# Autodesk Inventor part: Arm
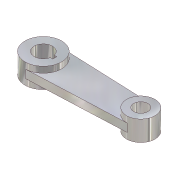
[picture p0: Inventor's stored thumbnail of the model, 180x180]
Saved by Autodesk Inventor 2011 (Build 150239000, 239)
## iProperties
Shininess: 77.0
Length Units: 11269
Angle Units: 11279
Time Units: 11290
Mass Units: 11283
Length Display Precision: 3
Angle Display Precision: 2
Created: 2002-01
Part Number: Arm
Document SubType Name: Modeling
Designer: ***
Density: 1 g/cm^3
Density: 0.0
Volumn: 0.0
Area: 0.0
PropertySet Name: Model Information
Control State: 0
Master: False
Checked Out: False
Author: ***
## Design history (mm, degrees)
sketch "Sketch1"
  geometry: L1 (-12.46, 6.114)-(-4.76, 6.114); L2 (-4.76, 6.114)-(-4.76, -6.486); L3 (-4.76, -6.486)-(-12.46, -6.486); L4 (-12.46, -6.486)-(-12.46, -6.885); C1 r 56.25 at (-39.849, -0.386); C2 r 43.75 at (260.151, -0.142); C3 r 21.9 at (260.151, -0.142); A1 r 28.15 centre (-39.849, -0.386) between (-12.46, 6.114) and (-12.46, -6.885)
  constraints: 8 end point, 4 centre point, 3 parallel, 2 coincident, 2 point on circle, 1 horizontal, 1 perpendicular
  dimensions: "d0" = 112.5 diameter of C1; "d1" = 300 distance of C2.centre C1.centre; "d2" = 87.5 diameter of C2; "d3" = 28.15 radius of A1; "d4" = 43.8 diameter of C3; "d5" = 12.6 distance of L1.end L2.end; "d6" = 7.7 distance of L2.end L3.end
extrude "Extrusion1" new body sketch "Sketch1" stored distance "d7" = 62.5; taper "d8" = 0 deg
sketch "Sketch2"
  geometry: L1 (-37.551, 55.817)-(261.939, 43.571); L2 (-37.46, -56.585)-(262.009, -43.853); C1 r 56.25 at (-39.849, -0.386) reference; C2 r 43.75 at (260.151, -0.142) reference; A1 r 56.25 centre (-39.849, -0.386) between (-37.46, -56.585) and (-37.551, 55.817); A2 r 43.75 centre (260.151, -0.142) between (261.939, 43.571) and (262.009, -43.853)
  constraints: 4 concentric, 4 end point, 4 point on circle, 4 tangent, 2 centre point
extrude "Extrusion2" join sketch "Sketch2" stored distance "d9" = 25.1; taper "d10" = 0 deg
body "Solid1"
